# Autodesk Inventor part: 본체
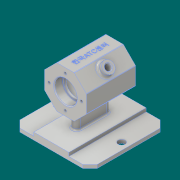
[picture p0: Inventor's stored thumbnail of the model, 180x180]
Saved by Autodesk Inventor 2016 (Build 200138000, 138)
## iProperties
Created: 2018-06
Part Number: 본체
Material: 알루미늄 6061
Document SubType Name: Modeling
Designer: 605-03
Mass: 552.311 g
Surface Area: 603.221 cm^2
Volume: 204.56 cm^3
Density: 2.7 g/cm^3
Appearance: 알루미늄 - 평지
Author: 605-03
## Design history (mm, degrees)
sketch "스케치1" dims "d0" = 60
  geometry: L1 (12.426, 30)-(30, 12.426); L2 (30, 12.426)-(30, -12.426); L3 (30, -12.426)-(12.426, -30); L4 (12.426, -30)-(-12.426, -30); L5 (-12.426, -30)-(-30, -12.426); L6 (-30, -12.426)-(-30, 12.426); L7 (-30, 12.426)-(-12.426, 30); L8 (-12.426, 30)-(12.426, 30); 4 further points
  constraints: 16 end point, 2 coincident, 1 midpoint, 1 vertical alignment, 19 other
  dimensions: "d1" = 17.57359 horizontal distance of L2.end L3.end
extrude "돌출1" new body sketch "스케치1" stored distance "d2" = 70; taper "d3" = 0 deg
sketch "스케치2"
  geometry: C1 r 16 at (0, 0); 1 further point
  constraints: 1 centre point, 1 coincident
  dimensions: "d4" = 32 diameter of C1
hole "구멍1" sketch "스케치2" at (0, 0) diameter "d5" = 32; stored, may be unused: countersink angle "d9" = 90 deg, drill point angle "d11" = 0 deg; dims "d6" = 6, "d7" = 4, "d8" = 2, "d10" = 12
sketch "스케치3"
  geometry: C1 r 16 at (0, 0) reference; C2 r 14 at (0, 0)
  constraints: 1 centre point, 1 coincident
  dimensions: "d12" = 28 diameter of C2
hole "구멍2" sketch "스케치3" at (0, 0) diameter "d13" = 28; stored, may be unused: countersink angle "d17" = 90 deg, drill point angle "d19" = 0 deg; dims "d14" = 6, "d15" = 4, "d16" = 2, "d18" = 3
sketch "스케치4"
  geometry: C1 r 14 at (0, 0) reference; C2 r 25 at (0, 0)
  constraints: 1 centre point, 1 coincident
  dimensions: "d20" = 50 diameter of C2
hole "구멍3" sketch "스케치4" at (0, 0) diameter "d21" = 50; stored, may be unused: countersink angle "d25" = 90 deg, drill point angle "d27" = 0 deg; dims "d22" = 6, "d23" = 4, "d24" = 2, "d26" = 40
fillet "모깎기1" dims "d28" = 0.3
fillet "모깎기2" dims "d29" = 3
fillet "모깎기3" dims "d30" = 1
sketch "스케치5" dims "d31" = 46
  geometry: C1 r 16 at (0, 0) reference; 2 further points
  constraints: 2 horizontal alignment, 1 coincident, 2 other
hole "구멍4" sketch "스케치5" at (23, 0) diameter "d32" = 3.242; stored, may be unused: countersink angle "d36" = 90 deg, drill point angle "d38" = 118 deg; dims "d33" = 8, "d34" = 4, "d35" = 2, "d37" = 10
node "작업 평면1"
sketch "스케치6"
  geometry: L1 (55, 55)-(55, -55); L2 (55, -55)-(-55, -55); L3 (-55, -55)-(-55, 55); L4 (-55, 55)-(55, 55); L5 (0, 0)-(0, -63.241); L6 (0, 0)-(61.775, 0); 2 further points
  constraints: 12 end point, 2 horizontal, 2 midpoint, 2 perpendicular, 2 point on line, 2 vertical
  dimensions: "d43" = 110 distance of L1.end L2.end; "d44" = 110 distance of L1.start L1.end
extrude "돌출2" join sketch "스케치6" distance "d46" = 5; taper "d47" = 0 deg
chamfer "모따기1" distance "d48" = 10; stored, may be unused: second distance "d49" = 2, angle "d50" = 45 deg
chamfer "모따기2" distance "d51" = 10; stored, may be unused: second distance "d52" = 2, angle "d53" = 45 deg
chamfer "모따기3" distance "d54" = 10; stored, may be unused: second distance "d55" = 2, angle "d56" = 45 deg
chamfer "모따기4" distance "d57" = 10; stored, may be unused: second distance "d58" = 2, angle "d59" = 45 deg
sketch "스케치7"
  geometry: L1 (45, 55)-(-45, 55) reference; L2 (-55, 45)-(-55, -45) reference; L3 (-45, -55)-(45, -55) reference; L4 (55, -45)-(55, 45) reference; L5 (45, -55)-(-45, -55) reference; L6 (-45, 55)-(45, 55) reference; L7 (-25, -55)-(-25, 55); L8 (25, 55)-(25, -55); 1 further point
  constraints: 4 end point, 4 point on line, 2 perpendicular
  dimensions: "d60" = 30 distance between parallel lines of L2 L7; "d61" = 30 distance between parallel lines of L4 L8
extrude "돌출3" join sketch "스케치7" distance "d62" = 5; taper "d63" = 0 deg
sketch "스케치8"
  geometry: L1 (0, -19)-(0, 19); L2 (5, -19)-(5, 19); L3 (-5, 19)-(-5, -19); A1 r 5 centre (0, -19) between (-5, -19) and (5, -19); A2 r 5 centre (0, 19) between (5, 19) and (-5, 19); 2 further points
  constraints: 6 end point, 4 point on circle, 3 coincident, 2 centre point, 2 tangent, 2 vertical, 1 midpoint, 1 parallel
  dimensions: "d64" = 38 distance of L1.start L1.end; "d65" = 10 diameter of A2; "d66" = 10 diameter of A1
extrude "돌출4" join sketch "스케치8" stored distance "d67" = 5; taper "d68" = 0 deg
fillet "모깎기4" dims "d69" = 2
sketch "스케치9"
  geometry: L1 (55, -45)-(55, 45) reference; L2 (55, 0)-(-55, 0); L3 (-55, -45)-(-55, 45) reference; C1 r 5 at (45, 0); 2 further points
  constraints: 2 end point, 2 midpoint, 1 centre point, 1 coincident, 1 point on line
  dimensions: "d70" = 10 distance from line of L1 point (45, 0); "d71" = 10 diameter of C1
hole "구멍5" sketch "스케치9" at (45, 0) diameter "d72" = 10; stored, may be unused: countersink angle "d76" = 90 deg, drill point angle "d78" = 0 deg; dims "d73" = 8, "d74" = 4, "d75" = 2, "d77" = 10
sketch "스케치10"
  geometry: C1 r 8 at (12.012, 35); 1 further point
  constraints: 1 centre point, 1 coincident
  dimensions: "d79" = 16 diameter of C1
extrude "돌출5" join sketch "스케치10" distance "d80" = 7; taper "d81" = 0 deg
sketch "스케치11"
  geometry: C1 r 8 at (0, 0) reference; C2 r 4 at (0, 0)
  constraints: 1 centre point, 1 coincident
  dimensions: "d82" = 8 diameter of C2
hole "구멍6" sketch "스케치11" at (0, 0) diameter "d83" = 8; stored, may be unused: countersink angle "d87" = 90 deg, drill point angle "d89" = 0 deg; dims "d84" = 8, "d85" = 4, "d86" = 2, "d88" = 10
fillet "모깎기5" dims "d90" = 3
sketch "스케치12"
  geometry: L1 (24.024, -70)-(0, -70) reference; L2 (-17.695, -70)-(-17.695, 0) reference; 2 further points
  constraints: 1 other
  dimensions: "d91" = 30 distance from line of L2 point (12.305, -35); "d92" = 35 distance from line of L1 point (12.305, -35)
feature "엠보싱1" sketch "스케치12" dims "d0" = 60, "d1" = 17.57359, "d93" = 0.5, "d94" = 0
chamfer "모따기5" distance "d95" = 1; stored, may be unused: second distance "d96" = 2, angle "d97" = 45 deg
chamfer "모따기6" distance "d98" = 1; stored, may be unused: second distance "d99" = 2, angle "d100" = 45 deg
chamfer "모따기7" distance "d101" = 1; stored, may be unused: second distance "d102" = 2, angle "d103" = 45 deg
node "솔리드1"
mirror "대칭1"
mirror "대칭2"
pattern_circular "원형 패턴1" dims angle "d40" = 360 deg
mirror "대칭3"
mirror "대칭4"
other parameters: "d42" = -62
